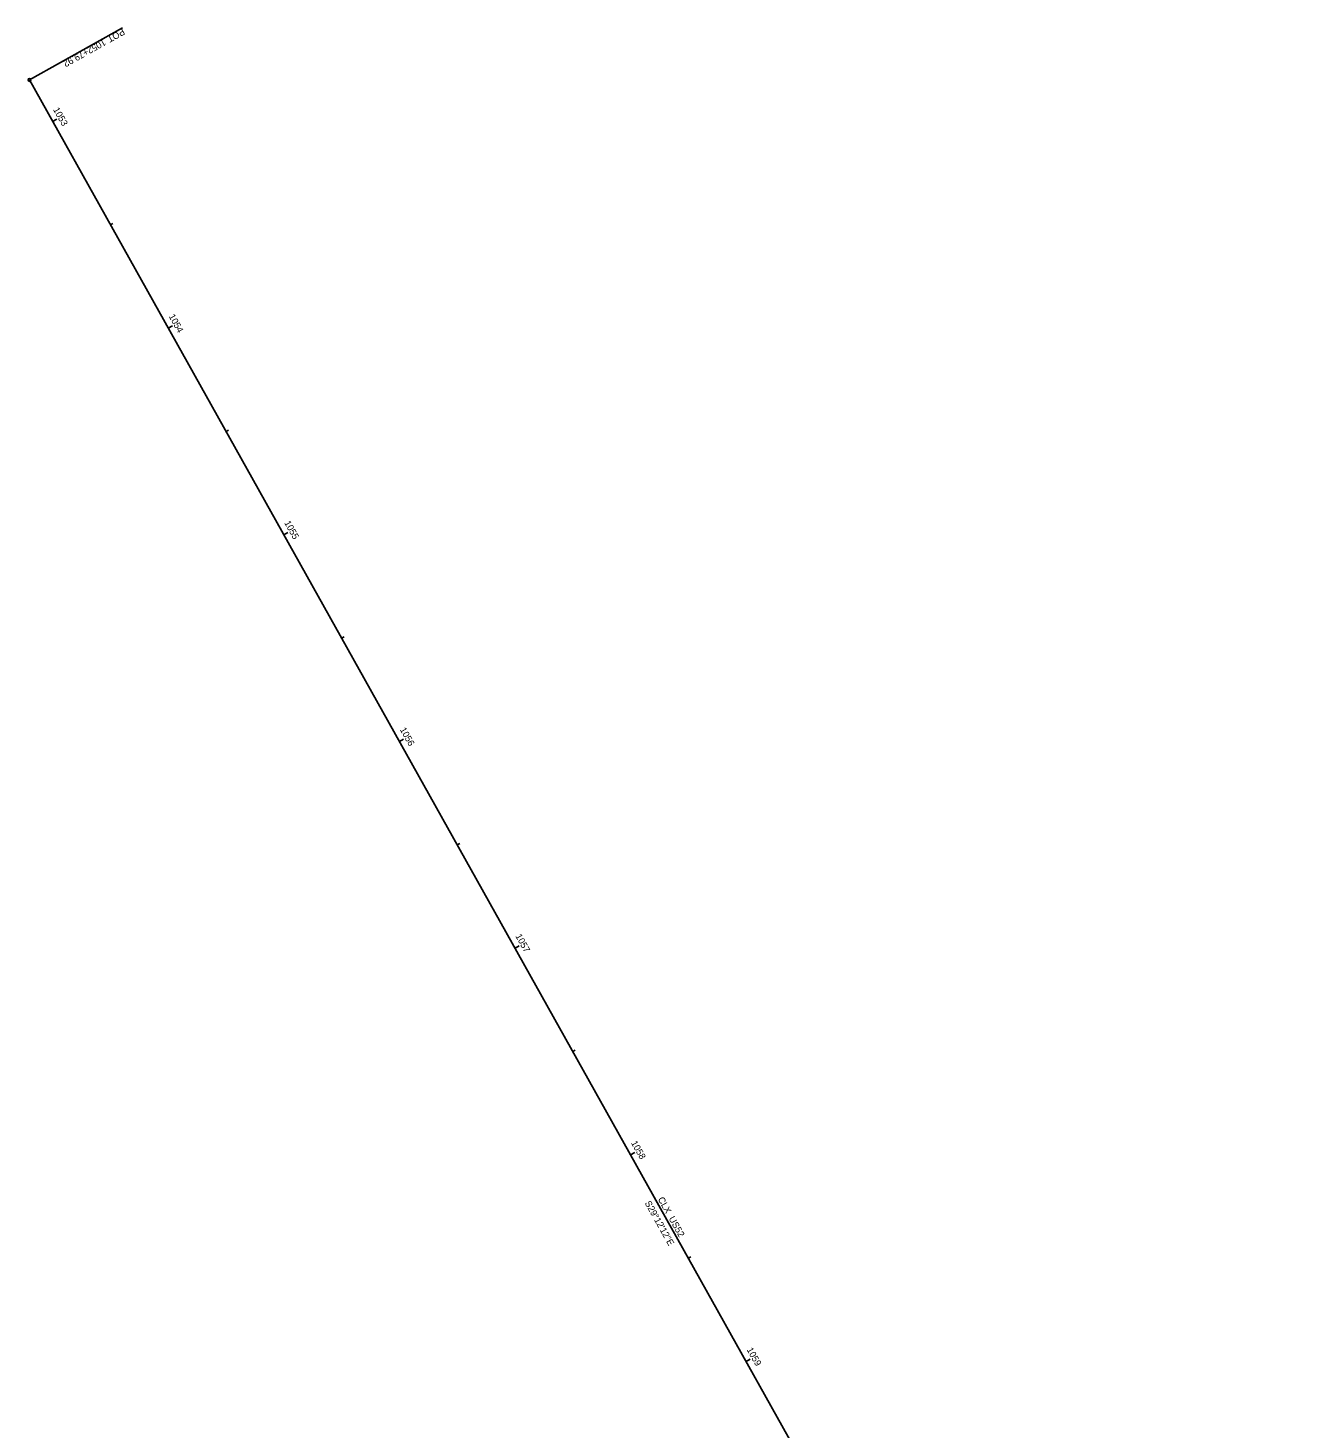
# Model space of a CAD drawing. Extents: x 1948127 to 1949841, y 151410 to 153356.
# Drawn here: x 1948127 to 1948666, y 152764 to 153356 of the extents above; entities that cross this region are included whole.
import ezdxf

# ---------------------------------------------------------------- set-up
doc = ezdxf.new("R2010")
doc.units = 0
for name, color, linetype in [('BR_P_Sub_Deep_Centerline', 7, 'Continuous'), ('BR_P_Sub_Deep_Hidden', 7, 'Continuous'), ('GE_P_Alignment', 7, 'Continuous'), ('SC_Scratch1', 7, 'Continuous'), ('SC_Scratch2', 7, 'Continuous')]:
    doc.layers.add(name, color=color, linetype=linetype)

msp = doc.modelspace()

# ---------------------------------------------------------------- linework, layer by layer
at = {"layer": 'BR_P_Sub_Deep_Centerline'}
for p, q in [((1948137.64, 153316.29), (1948139.39, 153317.27)), ((1948162.04, 153272.65), (1948163.09, 153273.23)), ((1948186.44, 153229), (1948188.18, 153229.98)), ((1948210.83, 153185.36), (1948211.88, 153185.94)), ((1948235.23, 153141.71), (1948236.97, 153142.69)), ((1948259.62, 153098.07), (1948260.67, 153098.66)), ((1948284.02, 153054.43), (1948285.76, 153055.4)), ((1948308.41, 153010.78), (1948309.46, 153011.37)), ((1948332.81, 152967.14), (1948334.55, 152968.11)), ((1948357.2, 152923.49), (1948358.25, 152924.08)), ((1948381.6, 152879.85), (1948383.35, 152880.82)), ((1948406, 152836.2), (1948407.04, 152836.79)), ((1948430.39, 152792.56), (1948432.14, 152793.53))]:
    msp.add_line(p, q, dxfattribs=at)
at = {"layer": 'BR_P_Sub_Deep_Hidden'}
msp.add_line((1948127.85, 153333.82), (1948167.13, 153355.78), dxfattribs=at)
msp.add_circle((1948127.85, 153333.82), 0.6, dxfattribs=at)
at = {"layer": 'SC_Scratch1'}
msp.add_line((1948127.85, 153333.82), (1948666.27, 152370.56), dxfattribs=at)

# ---------------------------------------------------------------- texts
at = {"layer": 'BR_P_Sub_Deep_Centerline'}
for s, p in [('1053', (1948137.74, 153321.33)), ('1054', (1948186.55, 153234.02)), ('1055', (1948235.31, 153146.78)), ('1056', (1948284.11, 153059.48)), ('1057', (1948332.87, 152972.24)), ('1058', (1948381.69, 152884.9)), ('1059', (1948430.5, 152797.59))]:
    msp.add_text(s, height=2.8, rotation=299.20338, dxfattribs=at).set_placement(p)
at = {"layer": 'BR_P_Sub_Deep_Hidden'}
for s, p in [('1052+79.92', (1948159.15, 153351.26)), ('POT', (1948167.12, 153355.72))]:
    msp.add_text(s, height=2.8, rotation=209.20338, dxfattribs=at).set_placement(p)
at = {"layer": 'GE_P_Alignment'}
msp.add_text('CLX_US52', height=2.8, rotation=299.20338, dxfattribs=at).set_placement((1948393, 152861.14))
at = {"layer": 'SC_Scratch2'}
msp.add_text('S29°12\'12"E', height=2.8, rotation=299.20338, dxfattribs=at).set_placement((1948387.47, 152859.51))

doc.saveas('drawing.dxf')
